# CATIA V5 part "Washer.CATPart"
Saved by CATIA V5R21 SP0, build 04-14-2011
Part number: washer
Bounding box of the stored display mesh (mm): x -24 to 24, y -23.825 to 23.825, z 0 to 3
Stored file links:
  D:\CATIA V5R21 E-RESOURCES\CATIA-V5R21\catia-v5r21-Prts\c12_catia_v5r21_prt\c12_catia_v5r21figr_12-53\Washer.CATPart
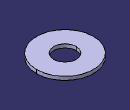
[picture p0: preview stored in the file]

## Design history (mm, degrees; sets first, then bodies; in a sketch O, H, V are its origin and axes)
Body1 (main body)
  Sketch1 on xy-plane, origin (0, 0, 0), H (1, 0, 0), V (0, 1, 0)
    circle A1 centre (0, 0) radius 24
    circle A2 centre (0, 0) radius 9.5
    radius A1 = 24
    radius A2 = 9.5
  Pad1: profile Sketch1, direction (0, 0, 1), length 3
